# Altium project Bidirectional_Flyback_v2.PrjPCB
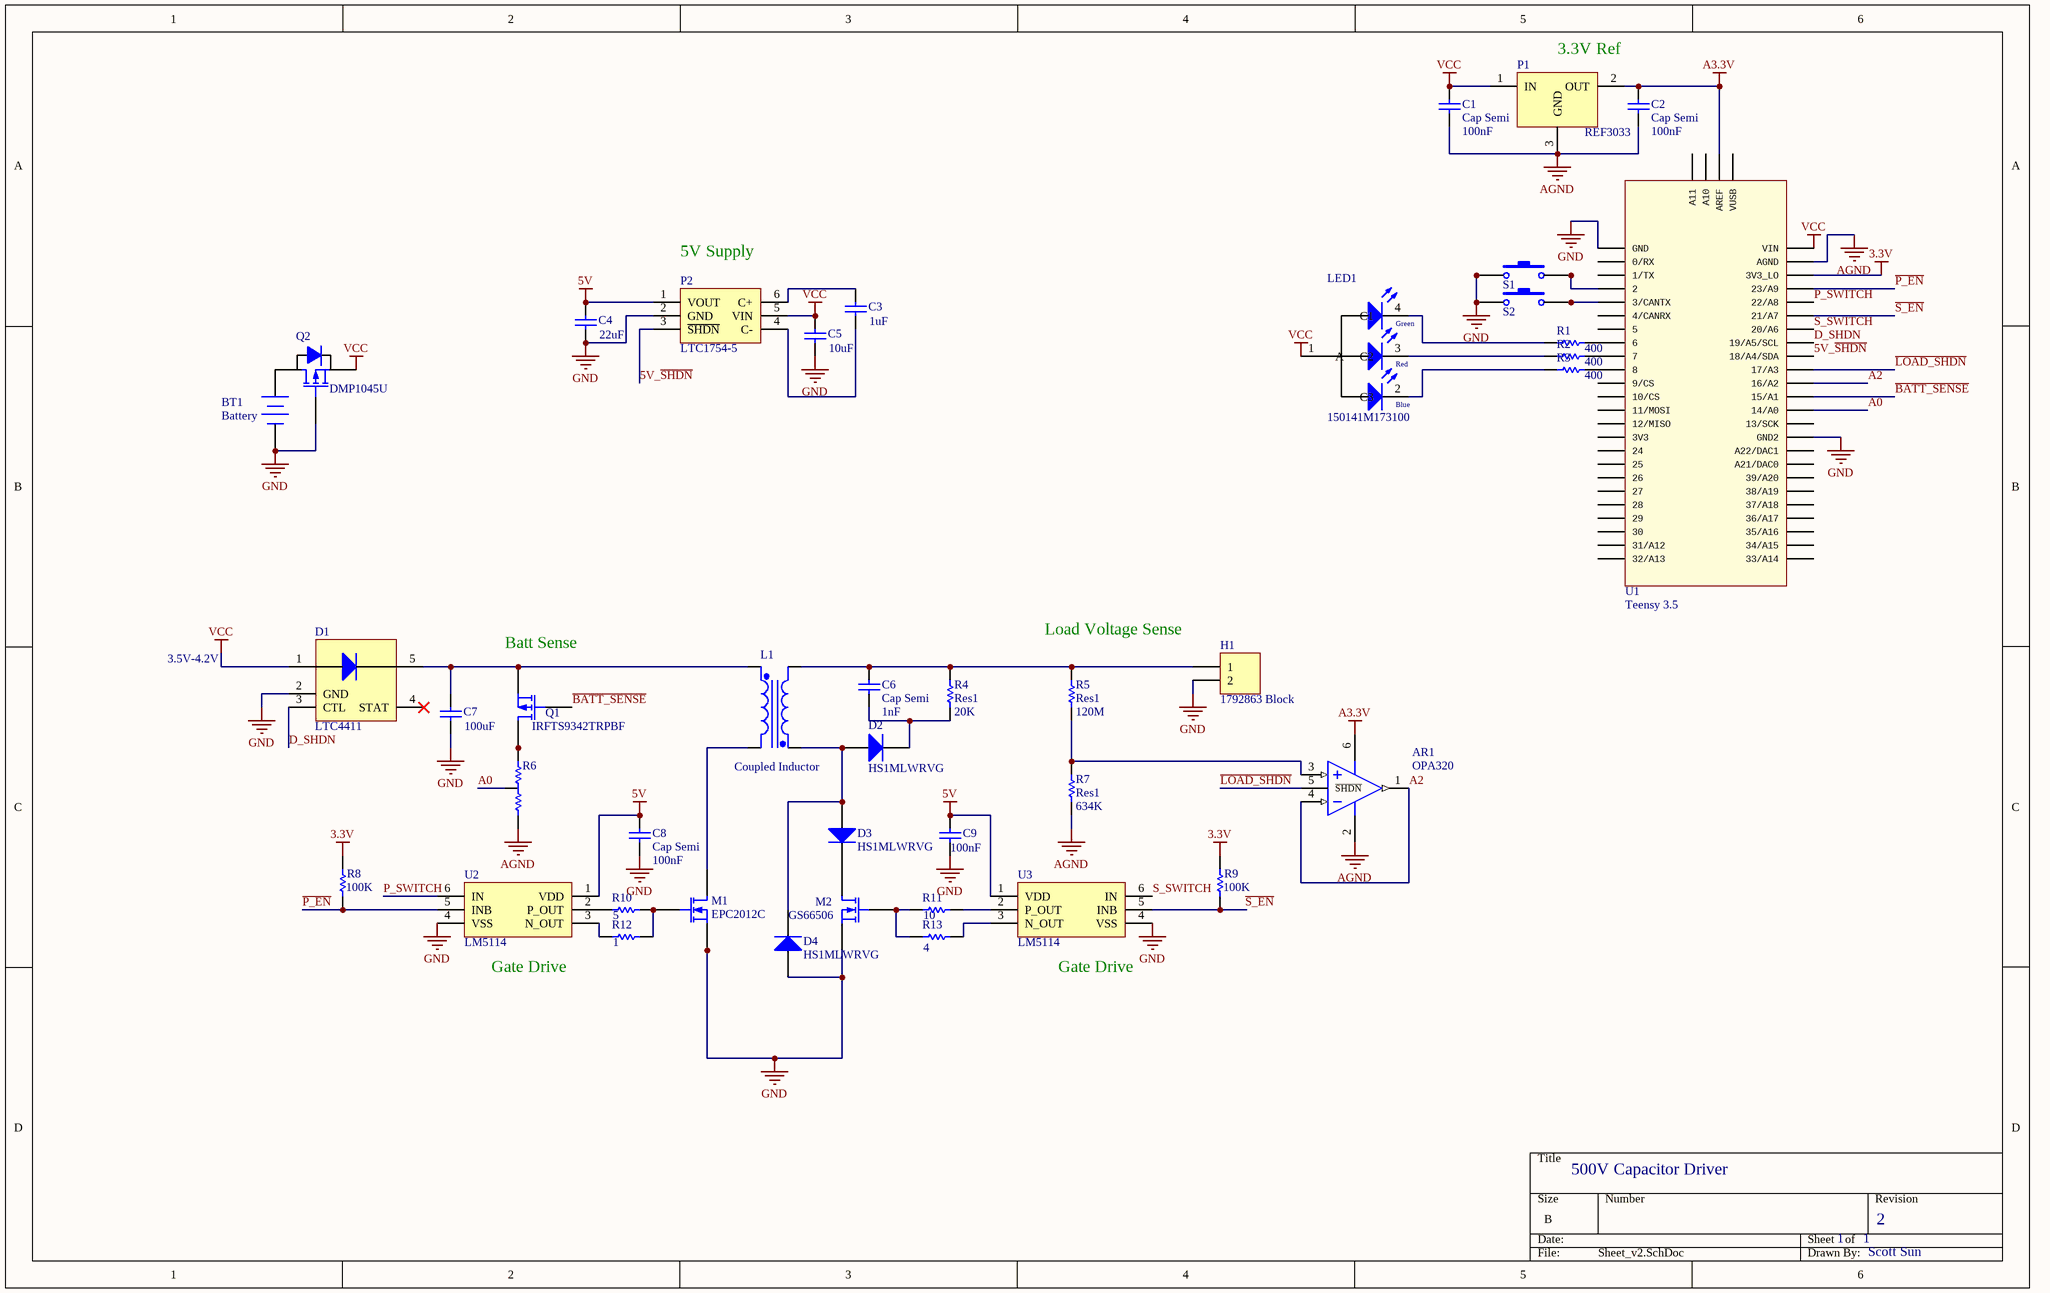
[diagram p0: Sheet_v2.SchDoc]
1 sheet, 42 parts. Net scope: global (net labels, ports and power ports of the same name join across sheets).
Board file: PCB_v2.PcbDoc

## Sheet Sheet_v2.SchDoc: 500V Capacitor Driver
size B; DrawnBy: Scott Sun; SheetNumber: 1; SheetTotal: 1

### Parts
AR1  OPA320  [SOT23-6_M]
BT1  Battery  [BAT-2]
C1  Cap Semi  value 100nF  [0603]
C2  Cap Semi  value 100nF  [0603]
C3  value 1uF  [0603]  (hidden comment: Cap Semi)
C4  value 22uF  [6-0805_N]  (hidden comment: Cap Semi)
C5  value 10uF  [6-0805_N]  (hidden comment: Cap Semi)
C6  Cap Semi  value 1nF  [6-0805_N]
C7  value 100uF  [C1210_N]  (hidden comment: Cap Semi)
C8  Cap Semi  value 100nF  [0603]
C9  value 100nF  [0603]  (hidden comment: Cap Semi)
D1  LTC4411  [SOT23-5]
D2  HS1MLWRVG  [sub-SMA]
D3  HS1MLWRVG  [sub-SMA]
D4  HS1MLWRVG  [sub-SMA]
H1  1792863 Block  [PHX_BLOCK_SMALLER]
L1  Coupled Inductor  [CJ5143 Inductor]
LED1  150141M173100  [3528_A]
M1  EPC2012C  [EPC2012C]
M2  GS66506  [GS66506T]
P1  REF3033  [SOT23_N]
P2  LTC1754-5  [SOT23-6_M]
Q1  IRFTS9342TRPBF  [SOT23-6_N]
Q2  DMP1045U  [SOT23_N]
R1  value 400  [0603]  (hidden comment: Res1)
R2  value 400  [0603]  (hidden comment: Res1)
R3  value 400  [0603]  (hidden comment: Res1)
R4  Res1  value 20K  [C1206]
R5  Res1  value 120M  [C1206]
R6  R2012A  [R2012A]  (value not drawn)
R7  Res1  value 634K  [6-0805_N]
R8  value 100K  [0603]  (hidden comment: Res1)
R9  value 100K  [0603]  (hidden comment: Res1)
R10  value 5  [0603]  (hidden comment: Res1)
R11  value 10  [0603]  (hidden comment: Res1)
R12  value 1  [0603]  (hidden comment: Res1)
R13  value 4  [0603]  (hidden comment: Res1)
S1  TL3365  [TL3365]  (value not drawn)
S2  TL3365  [TL3365]  (value not drawn)
U1  Teensy 3.5  [Teensy 3.6]
U2  LM5114  [SOT23-6_N]
U3  LM5114  [SOT23-6_N]

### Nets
3.3V: R8.2 R9.2 U1.3V3_LO
5V: C4.2 C8.2 C9.2 P2.1(VOUT) U2.1(VDD) U3.1(VDD)
A3.3V: AR1.6(V+) C2.2 P1.2(OUT) U1.AREF
AGND: AR1.2(V-) C1.1 C2.1 P1.3(GND) R6.3 R7.1 U1.AGND
GND: BT1.2(-) C4.1 C5.1 C7.1 C8.1 C9.1 D1.2(GND) D4.A H1.2 M1.2(S) M1.4(S) M2.3(S) P2.2(GND) Q2.3(G) S1.1 S1.2 S2.1 S2.2 U1.GND U1.GND2 U2.4(VSS) U3.4(VSS)
VCC: C1.2 C5.2 D1.1(IN) LED1.1(A) P1.1(IN) P2.5(VIN) Q2.2(S) U1.VIN
5V_~{SHDN}: P2.3(~{SHDN}) U1.18/A4/SDA
A0: R6.2 U1.14/A0
A2: AR1.1(OUT) AR1.4(IN-) U1.16/A2
~{BATT_SENSE}: Q1.3(G) U1.15/A1
D_SHDN: D1.3(CTL) U1.19/A5/SCL
~{LOAD_SHDN}: AR1.5(~{SHDN}) U1.17/A3
~{P_EN}: R8.1 U1.23/A9 U2.5(INB)
P_SWITCH: U1.22/A8 U2.6(IN)
~{S_EN}: R9.1 U1.21/A7 U3.5(INB)
S_SWITCH: U1.20/A6 U3.6(IN)
NetAR1_3: AR1.3(IN+) R5.1 R7.2
NetBT1_1: BT1.1(+) Q2.1(D)
NetC3_1: C3.1 P2.4(C-)
NetC3_2: C3.2 P2.6(C+)
NetC6_1: C6.1 D2.K R4.1
NetC6_2: C6.2 H1.1 L1.5(Sec-) R4.2 R5.2
NetC7_2: C7.2 D1.5(OUT) L1.1(Pri+) Q1.4(S)
NetD2_A: D2.A D3.A D4.K L1.6(Sec+)
NetD3_K: D3.K M2.1(D)
NetL1_4: L1.4(Pri-) M1.3(D)
NetLED1_2: LED1.2(C3) R3.2
NetLED1_3: LED1.3(C2) R2.2
NetLED1_4: LED1.4(C1) R1.2
NetM1_1: M1.1(G) R10.1 R12.1
NetM2_2: M2.2(G) M2.4(G) R11.2 R13.2
NetQ1_1: Q1.1(D) Q1.2(D) Q1.5(D) Q1.6(D) R6.1
NetR1_1: R1.1 U1.6
NetR2_1: R2.1 U1.7
NetR3_1: R3.1 U1.8
NetR10_2: R10.2 U2.2(P_OUT)
NetR11_1: R11.1 U3.2(P_OUT)
NetR12_2: R12.2 U2.3(N_OUT)
NetR13_1: R13.1 U3.3(N_OUT)
NetS1_3: S1.3 S1.4 U1.2
NetS2_3: S2.3 S2.4 U1.3/CANTX

Not connected (* = marked no-connect by the designer): D1 4(STAT)*; U1 0/RX 1/TX 3V3 4/CANRX 5 9/CS 10/CS 11/MOSI 12/MISO 13/SCK 21/DAC0(A21/DAC0) 24 25 26 27 28 29 30 31/A12 32/A13 33/A14 34/A15 35/A16 36/A17 37/A18 38/A19 39/A20 A10 A11 A22/DAC1 VUSB

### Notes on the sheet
- 3.3V Ref
- (near P2) 5V Supply
- Load Voltage Sense
- 3.5V-4.2V
- (near Q1) Batt Sense
- Gate Drive
- (near U3) Gate Drive
- 1
- 2

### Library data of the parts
AR1 = OPA320 Op Amp: FET Operational Amplifier
BT1 = Battery: Multicell Battery
C1-C9 = Cap Semi: Capacitor (Semiconductor SIM Model)
D1 = LTC4411 Ideal Diode
D2-D4 = HS1MLWRVG Diode: 1kV fast diode
H1 = 1792863 1X2 Block: Terminal Block, 2-Pin, 1792863
L1 = CJ5143 Coupled Inductor: 1:15 Coupled Inductor
LED1 = CMP-1431-00001-1: SMD Full-Color Top LED, WL-SFTW, Red & Green & Blue; Manufacturer: Wuerth Elektronik
M1 = EPC2012C GaNFET: 200V GaNFET Die
M2 = GS66506 GaNFET: 650V GaNFET
P1 = REF3030 3V Reference: 3.3V Reference; pin to pad: 1>3 3>1
P2 = LTC1754-5 Charge Pump: 5V Charge Pump
Q1 = IRFTS9342TRPBF MOSFET: 30V, 5.8A, P-Channel MOSFET
Q2 = DMP1045U PMOS: P-Channel MOSFET
R1-R5 R7-R13 = Res1: Resistor
R6 = R2012A Voltage Divider: Voltage Divider
S1 S2 = TL3365 Pushbutton: Pushbutton
U1 = TEENSY_3.6: Teensy 3.6 Microcontroller
U2 U3 = LM5114 Gate Driver: Gate Driver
